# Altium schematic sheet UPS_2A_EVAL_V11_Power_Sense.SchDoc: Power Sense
size A4; CompanyName: Hedgehog OÜ; Revision: 1; SheetNumber: 4; SheetTotal: 5; DrawnBy: Peep Narusberg; Engineer: Peep Narusberg; Organization: Hedgehog OÜ; Address1: Waterloohain 5; Address2: 22769 Hamburg; Address3: Germany; Address4: tmc_info@trinamic.com
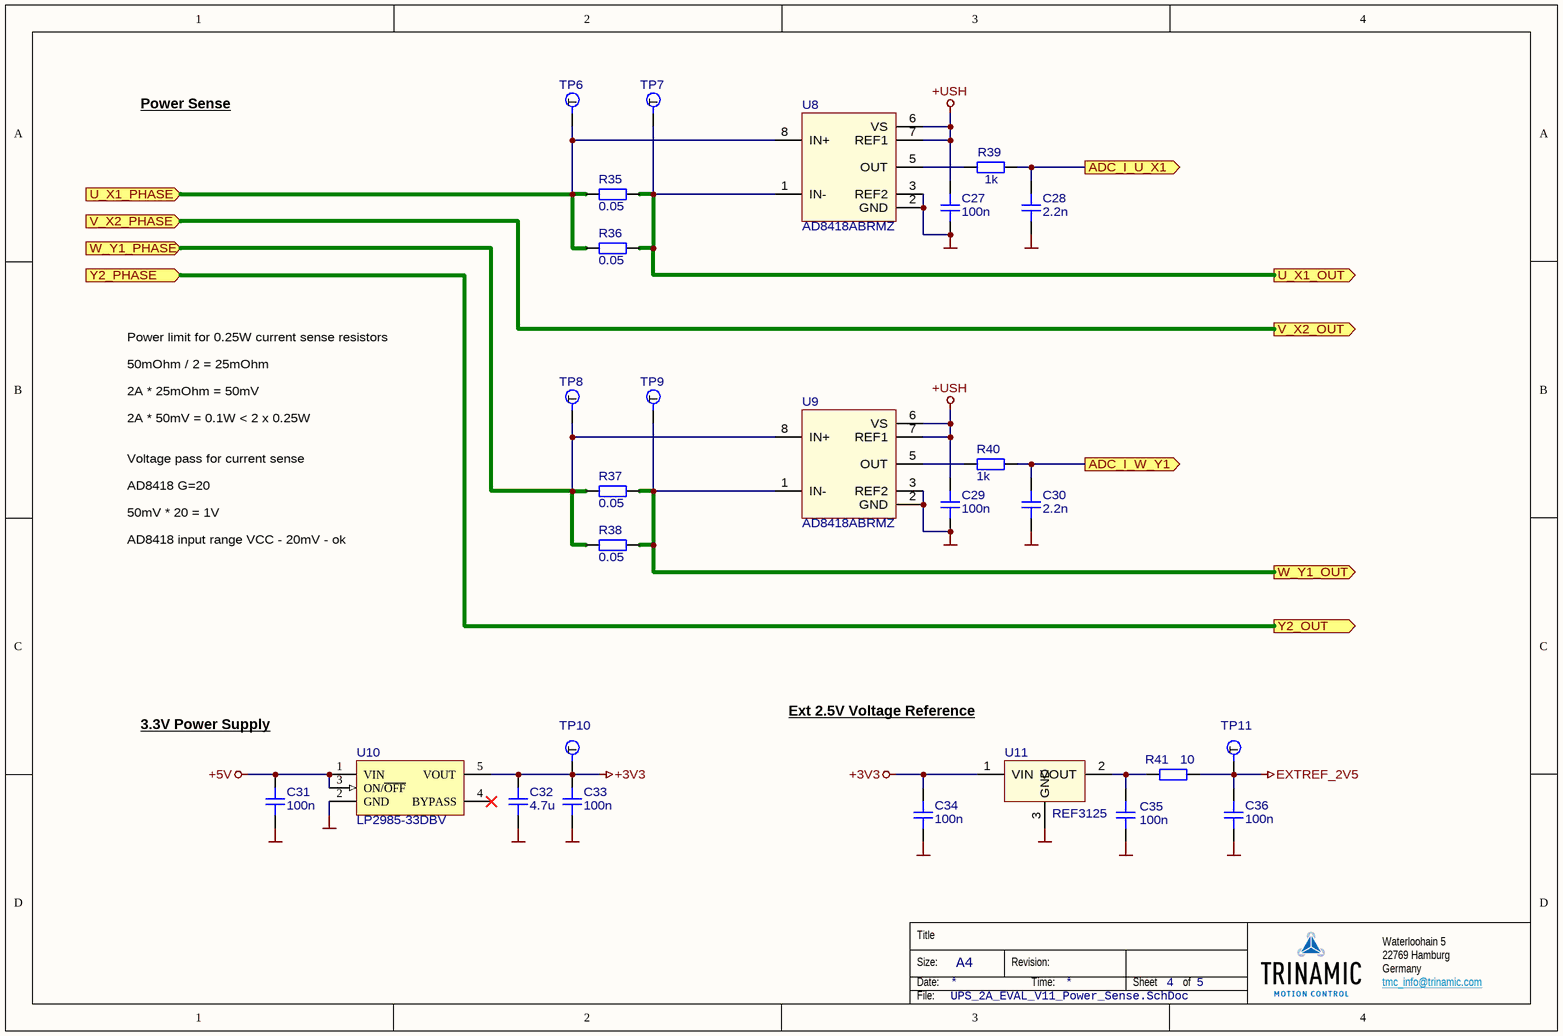
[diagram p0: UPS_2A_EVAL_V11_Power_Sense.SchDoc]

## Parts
C27  value 100n  [CAPC1608N]  (hidden comment: CAPC)
C28  value 2.2n  [CAPC1608N]
C29  value 100n  [CAPC1608N]  (hidden comment: CAPC)
C30  value 2.2n  [CAPC1608N]
C31  value 100n  [CAPC1608N]  (hidden comment: CAPC)
C32  value 4.7u  [CAPC1608N]  (hidden comment: CAPC)
C33  value 100n  [CAPC1608N]  (hidden comment: CAPC)
C34  value 100n  [CAPC1608N]  (hidden comment: CAPC)
C35  value 100n  [CAPC1608N]  (hidden comment: CAPC)
C36  value 100n  [CAPC1608N]  (hidden comment: CAPC)
R35  value 0.05  [RESC2012N]  (hidden comment: RESC)
R36  value 0.05  [RESC2012N]  (hidden comment: RESC)
R37  value 0.05  [RESC2012N]  (hidden comment: RESC)
R38  value 0.05  [RESC2012N]  (hidden comment: RESC)
R39  value 1k  [RESC1608N]  (hidden comment: RESC)
R40  value 1k  [RESC1608N]  (hidden comment: RESC)
R41  value 10  [RESC1608N]  (hidden comment: RESC)
TP6  SENSE_X+  [TP100P254]  (value not drawn)  (no BOM)
TP7  SENSE_X-  [TP100P254]  (value not drawn)  (no BOM)
TP8  SENSE_Y+  [TP100P254]  (value not drawn)  (no BOM)
TP9  SENSE_Y-  [TP100P254]  (value not drawn)  (no BOM)
TP10  +3V3  [TP100P254]  (value not drawn)  (no BOM)
TP11  EXTREF 2V5  [TP100P254]  (value not drawn)  (no BOM)
U8  Part Number: AD8418ABRMZ  [TSOP65P490X95-8N]  (hidden comment: *)
U9  Part Number: AD8418ABRMZ  [TSOP65P490X95-8N]  (hidden comment: *)
U10  Part Number: LP2985-33DBV  [SOT95P270X145-5N]
U11  Part Number: REF3125  [SOT95P280X130-3N]  (hidden comment: *)

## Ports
ADC_I_U_X1 (out), ADC_I_W_Y1 (out), U_X1_OUT (out), U_X1_PHASE (in), V_X2_OUT (out), V_X2_PHASE (in), W_Y1_OUT (out), W_Y1_PHASE (in), Y2_OUT (out), Y2_PHASE (in)

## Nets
+3V3: C32.2 C33.2 C34.2 TP10.1(T) U10.5(VOUT) U11.1(VIN)
+5V: C31.2 U10.1(VIN) U10.3(ON/~{OFF})
+USH: C27.1 C29.2 U8.6(VS) U8.7(REF1) U9.6(VS) U9.7(REF1)
EXTREF_2V5: C36.2 R41.2 TP11.1(T)
GND: C27.2 C28.1 C29.1 C30.1 C31.1 C32.1 C33.1 C34.1 C35.1 C36.1 U8.2(GND) U8.3(REF2) U9.2(GND) U9.3(REF2) U10.2(GND) U11.3(GND)
ADC_I_U_X1: C28.2 R39.2 ; port ADC_I_U_X1
ADC_I_W_Y1: C30.2 R40.2 ; port ADC_I_W_Y1
U_X1_OUT: R35.2 R36.2 TP7.1(T) U8.1(IN-) ; port U_X1_OUT
U_X1_PHASE: R35.1 R36.1 TP6.1(T) U8.8(IN+) ; port U_X1_PHASE
V_X2_OUT: port V_X2_PHASE, port V_X2_OUT
W_Y1_OUT: R37.2 R38.2 TP9.1(T) U9.1(IN-) ; port W_Y1_OUT
W_Y1_PHASE: R37.1 R38.1 TP8.1(T) U9.8(IN+) ; port W_Y1_PHASE
Y2_OUT: port Y2_PHASE, port Y2_OUT
NetC35_2: C35.2 R41.1 U11.2(VOUT)
NetR39_1: R39.1 U8.5(OUT)
NetR40_1: R40.1 U9.5(OUT)

Not connected (* = marked no-connect by the designer): U10 4(BYPASS)*

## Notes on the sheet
- Power Sense
- Power limit for 0.25W current sense resistors
  50mOhm / 2 = 25mOhm
  2A * 25mOhm = 50mV
  2A * 50mV = 0.1W < 2 x 0.25W
  Voltage pass for current sense
  AD8418 G=20
  50mV * 20 = 1V
  AD8418 input range VCC - 20mV - ok
- Ext 2.5V Voltage Reference
- 3.3V Power Supply

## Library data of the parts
C27 C29 C31 C33-C36 = 20027: Ceramic chip capacitor; Manufacturer: Any; Part Number: 100n, 50V, X5R, 0603 (1608 metric) chip capacitor; Id: 20027; Voltage: 50V
C28 C30 = 20056: Ceramic chip capacitor; Manufacturer: Any; Part Number: 2.2n, 50V, C0G/NP0, 0603 (1608 metric) chip capacitor; Id: 20056; Voltage: 50V
C32 = 20084: Ceramic chip capacitor; Manufacturer: Any; Part Number: 4.7u, 10V, X5R, 0603 (1608 metric) chip capacitor; Id: 20084; Voltage: 10V
R35-R38 = 10172: Chip Resistor; Manufacturer: Any; Part Number: 0.05, 1%, 250mW, 0805 (2012 metric) chip resistor; Id: 10172; Power: 250mW; Tolerance: 1%
R39 R40 = 10049: Chip Resistor; Manufacturer: Any; Part Number: 1k, 1%, 100mW, 0603 (1608 metric) chip resistor; Id: 10049; Power: 100mW; Tolerance: 1%
R41 = 10002: Chip Resistor; Manufacturer: Any; Part Number: 10, 1%, 100mW, 0603 (1608 metric) chip resistor; Id: 10002; Power: 100mW; Tolerance: 1%
TP6-TP11 = 50094: Round testpoint; Id: 50094; Value: c160 (P100 probe)
U8 U9 = 50496: Bidirectional, Zero Drift, Current Sense Amplifier; Manufacturer: Analog Devices; Id: 50496; Value: CMVR=70V
U10 = 50426: 150-mA Low-noise LDO; Manufacturer: Texas Instruments; Id: 50426; Value: 150mA 3.3V
U11 = 50316: Series voltage reference; Manufacturer: Texas Instruments; Id: 50316; Value: 2.5V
